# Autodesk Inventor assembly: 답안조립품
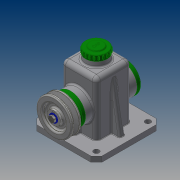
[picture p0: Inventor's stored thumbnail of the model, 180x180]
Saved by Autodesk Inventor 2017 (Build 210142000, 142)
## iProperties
Part Number: 답안조립품
Material: 일반
Document SubType Name: Assembly
Designer: 20
Author: 20
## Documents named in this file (14)
- C:\Users\20\Desktop\470818V1014\답안조립품.iam
- C:\Users\20\Desktop\470818V1014\본체.ipt
- C:\Users\20\Desktop\470818V1014\상부캡.ipt
- C:\Users\20\Desktop\470818V1014\앞커버.ipt
- C:\Users\20\Desktop\470818V1014\뒤커버.ipt
- C:\Users\20\Desktop\470818V1014\베어링 15 x 35 x 11.ipt
- C:\Users\20\Desktop\470818V1014\멈춤링 15 x 1.ipt
- C:\Users\20\Desktop\470818V1014\오일실 15 25 7.ipt
- C:\Users\20\Desktop\470818V1014\볼트 M4 x 10.ipt
- C:\Users\20\Desktop\470818V1014\축.ipt
- C:\Users\20\Desktop\470818V1014\키 5 x 5 x 14.ipt
- C:\Users\20\Desktop\470818V1014\V-벨트풀리.ipt
- C:\Users\20\Desktop\470818V1014\와셔.ipt
- C:\Users\20\Desktop\470818V1014\볼트 M6 x 12.ipt
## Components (1 placed, 1 different names)
1. V-벨트풀리:1 — 플러쉬:2
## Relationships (1: Flush 1)
- 플러쉬:2 [Flush]: V-벨트풀리:1
